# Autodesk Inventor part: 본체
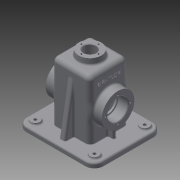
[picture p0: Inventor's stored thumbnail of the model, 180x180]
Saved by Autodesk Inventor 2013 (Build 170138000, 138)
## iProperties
Created: 2016-01
Part Number: 본체
Material: 일반
Document SubType Name: Modeling
Designer: Administrator
Density: 1 g/cm^3
Author: Administrator
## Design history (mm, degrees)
sketch "스케치1"
  geometry: L1 (-65, -57.5)-(65, -57.5); L2 (65, -57.5)-(65, 57.5); L3 (65, 57.5)-(-65, 57.5); L4 (-65, 57.5)-(-65, -57.5); 3 further points
  constraints: 8 end point, 2 midpoint, 2 parallel, 1 horizontal, 1 horizontal alignment, 1 perpendicular, 1 vertical alignment
  dimensions: "d0" = 130 distance of L2.end L3.end; "d2" = 115 distance of L1.end L2.end
extrude "돌출1" new body sketch "스케치1" distance "d3" = 8; taper "d4" = 0 deg
fillet "모깎기1" dims "d5" = 15
sketch "스케치2"
  geometry: L1 (-65, -42.5)-(-65, 42.5) reference; L2 (50, -57.5)-(-50, -57.5) reference; L3 (65, 42.5)-(65, -42.5) reference; L4 (-50, 57.5)-(50, 57.5) reference; L5 (-65, -42.5)-(-65, 42.5) reference; L6 (50, -57.5)-(-50, -57.5) reference; L7 (65, 42.5)-(65, -42.5) reference; L8 (-50, 57.5)-(50, 57.5) reference; L9 (-60, -42.5)-(-60, 42.5); L10 (-50, 52.5)-(50, 52.5); L11 (60, 42.5)-(60, -42.5); L12 (50, -52.5)-(-50, -52.5); A1 r 15 centre (-50, 42.5) between (-50, 57.5) and (-65, 42.5) reference; A2 r 15 centre (-50, -42.5) between (-65, -42.5) and (-50, -57.5) reference; A3 r 15 centre (50, -42.5) between (50, -57.5) and (65, -42.5) reference; A4 r 15 centre (50, 42.5) between (65, 42.5) and (50, 57.5) reference; A5 r 15 centre (-50, 42.5) between (-50, 57.5) and (-65, 42.5) reference; A6 r 15 centre (-50, -42.5) between (-65, -42.5) and (-50, -57.5) reference; A7 r 15 centre (50, -42.5) between (50, -57.5) and (65, -42.5) reference; A8 r 15 centre (50, 42.5) between (65, 42.5) and (50, 57.5) reference; A9 r 10 centre (-50, -42.5) between (-60, -42.5) and (-50, -52.5); A10 r 10 centre (-50, 42.5) between (-50, 52.5) and (-60, 42.5); A11 r 10 centre (50, 42.5) between (60, 42.5) and (50, 52.5); A12 r 10 centre (50, -42.5) between (50, -52.5) and (60, -42.5); 1 further point
  constraints: 8 end point, 8 point on circle, 4 centre point, 7 other
  dimensions: "d6" = 5 distance between parallel lines of L2 L12
extrude "돌출2" join sketch "스케치2" distance "d7" = 2; taper "d8" = 0 deg
sketch "스케치3"
  geometry: A1 r 10 centre (-50, -42.5) between (-60, -42.5) and (-50, -52.5) reference; A2 r 10 centre (50, -42.5) between (50, -52.5) and (60, -42.5) reference; A3 r 10 centre (50, 42.5) between (60, 42.5) and (50, 52.5) reference; A4 r 10 centre (-50, 42.5) between (-50, 52.5) and (-60, 42.5) reference; 1 further point
hole "구멍1" sketch "스케치3" at (50, -42.5), (-50, -42.5), (-50, 42.5), (50, 42.5) diameter "d9" = 5; stored, may be unused: countersink angle "d13" = 90 deg, drill point angle "d15" = 0 deg; dims "d10" = 6, "d11" = 4, "d12" = 2, "d14" = 13
sketch "스케치4"
  geometry: C1 r 2.5 at (50, 42.5) reference; C2 r 2.5 at (-50, -42.5) reference; C3 r 2.5 at (50, -42.5) reference; C4 r 2.5 at (-50, 42.5) reference; C5 r 7.5 at (-50, 42.5); C6 r 7.5 at (50, 42.5); C7 r 7.5 at (50, -42.5); C8 r 7.5 at (-50, -42.5); A1 r 15 centre (50, 42.5) between (65, 42.5) and (50, 57.5) reference; A2 r 15 centre (-50, 42.5) between (-50, 57.5) and (-65, 42.5) reference; A3 r 15 centre (-50, -42.5) between (-65, -42.5) and (-50, -57.5) reference; A4 r 15 centre (50, -42.5) between (50, -57.5) and (65, -42.5) reference; 1 further point
  constraints: 4 centre point, 4 coincident
  dimensions: "d16" = 15 diameter of C5; "d17" = 15 diameter of C6; "d18" = 15 diameter of C7; "d19" = 15 diameter of C8
extrude "돌출3" join sketch "스케치4" distance "d20" = 3; taper "d21" = 0 deg
fillet "모깎기2" dims "d22" = 3
fillet "모깎기3" dims "d23" = 3
sketch "스케치5"
  geometry: L1 (-32.5, 32.5)-(32.5, 32.5); L2 (32.5, 32.5)-(32.5, -32.5); L3 (32.5, -32.5)-(-32.5, -32.5); L4 (-32.5, -32.5)-(-32.5, 32.5); 3 further points
  constraints: 8 end point, 2 midpoint, 2 parallel, 1 horizontal, 1 horizontal alignment, 1 perpendicular, 1 vertical alignment
  dimensions: "d24" = 65 distance of L1.start L1.end; "d26" = 65 distance of L3.end L1.start
extrude "돌출4" join sketch "스케치5" distance "d27" = 100; taper "d28" = 0 deg
sketch "스케치6"
  geometry: L1 (27.5, -27.5)-(-27.5, -27.5); L2 (-27.5, -27.5)-(-27.5, 27.5); L3 (-27.5, 27.5)-(27.5, 27.5); L4 (27.5, 27.5)-(27.5, -27.5); 3 further points
  constraints: 8 end point, 2 midpoint, 2 parallel, 1 horizontal, 1 horizontal alignment, 1 perpendicular, 1 vertical alignment
  dimensions: "d31" = 55 distance of L1.start L1.end; "d33" = 55 distance of L3.end L1.start
extrude "돌출5" cut sketch "스케치6" distance "d34" = 105; taper "d35" = 0 deg
sketch "스케치7"
  geometry: C1 r 20 at (0, 0); 1 further point
  constraints: 1 centre point, 1 coincident
  dimensions: "d36" = 40 diameter of C1
extrude "돌출6" join sketch "스케치7" distance "d37" = 10; taper "d38" = 0 deg
feature "면 기울기1" dims angle "d39" = 5 deg
fillet "모깎기6" dims "d40" = 3
sketch "스케치8"
  geometry: C1 r 19.125 at (0, 0) reference; C2 r 10.5 at (0, 0)
  constraints: 1 centre point, 1 coincident
  dimensions: "d41" = 21 diameter of C2
extrude "돌출7" cut sketch "스케치8" distance "d42" = 15; taper "d43" = 0 deg
chamfer "모따기1" distance "d44" = 1; stored, may be unused: second distance "d45" = 2, angle "d46" = 45 deg
sketch "스케치9" dims "d47" = 29
  geometry: L1 (0, 0)-(0, 14.5); C1 r 11.5 at (0, 0) reference; 1 further point
  constraints: 2 coincident, 2 end point, 1 vertical, 1 vertical alignment, 2 other
hole "구멍2" sketch "스케치9" at (0, 14.5) diameter "d48" = 2.459; stored, may be unused: countersink angle "d52" = 90 deg, drill point angle "d54" = 118 deg; dims "d49" = 7, "d50" = 4, "d51" = 2, "d53" = 9
sketch "스케치10"
  geometry: L1 (10, -28)-(8, -28) reference; L2 (8, -28)-(8, -33) reference; L3 (8, -33)-(3, -33) reference; L4 (0, -30)-(0, -8) reference; L5 (0, 57)-(0, 79) reference; L6 (3, 82)-(8, 82) reference; L7 (8, 82)-(8, 77) reference; L8 (8, 77)-(10, 77) reference; L9 (10, 77)-(10, -28) reference; L10 (10, -28)-(8, -28) reference; L11 (8, -28)-(8, -33) reference; L12 (8, -33)-(3, -33) reference; L13 (0, -30)-(0, -8) reference; L14 (0, 57)-(0, 79) reference; L15 (3, 82)-(8, 82) reference; L16 (8, 82)-(8, 77) reference; L17 (8, 77)-(10, 77) reference; L18 (10, 77)-(10, -28) reference; L19 (0, -8)-(-100, -8) reference; L20 (-100, 57)-(0, 57) reference; L21 (0, -8)-(0, 57) reference; L22 (0, -8)-(-100, -8) reference; L23 (-100, 57)-(0, 57) reference; L24 (0, -8)-(0, 57) reference; L25 (-100, -8)-(-100, 57) reference; L26 (-100, -8)-(-100, 57) reference; C1 r 27.5 at (-45, 24.5); A1 r 3 centre (3, -30) between (0, -30) and (3, -33) reference; A2 r 3 centre (3, 79) between (3, 82) and (0, 79) reference; A3 r 3 centre (3, -30) between (0, -30) and (3, -33) reference; A4 r 3 centre (3, 79) between (3, 82) and (0, 79) reference; 2 further points
  constraints: 1 centre point, 1 horizontal alignment, 1 midpoint
  dimensions: "d58" = 55 diameter of C1; "d59" = 55 distance of point (10, 24.5) C1.centre
extrude "돌출8" join sketch "스케치10" distance "d60" = 15; taper "d61" = 0 deg
sketch "스케치11"
  geometry: C1 r 27.5 at (0, 0) reference; C2 r 17.5 at (0, 0); 1 further point
  constraints: 1 centre point, 1 coincident
  dimensions: "d62" = 35 diameter of C2
extrude "돌출9" cut sketch "스케치11" distance "d63" = 17; taper "d64" = 0 deg
sketch "스케치12" dims "d65" = 42
  geometry: L1 (0, 0)-(-21, 0); C1 r 27.5 at (0, 0) reference; 2 further points
  constraints: 2 coincident, 2 end point, 1 horizontal, 1 horizontal alignment, 2 other
hole "구멍3" sketch "스케치12" at (-21, 0) diameter "d66" = 3.242; stored, may be unused: countersink angle "d70" = 90 deg, drill point angle "d72" = 118 deg; dims "d67" = 8, "d68" = 4, "d69" = 2, "d71" = 10
sketch "스케치13"
  geometry: C1 r 17.5 at (0, 0) reference; C2 r 15 at (0, 0); 1 further point
  constraints: 1 centre point, 1 coincident
  dimensions: "d76" = 30 diameter of C2
extrude "돌출10" cut sketch "스케치13" distance "d77" = 3; taper "d78" = 0 deg
chamfer "모따기2" distance "d79" = 1; stored, may be unused: second distance "d80" = 2, angle "d81" = 45 deg
fillet "모깎기7" dims "d82" = 0.3
fillet "모깎기8" dims "d83" = 3
fillet "모깎기9" dims "d84" = 3
node "작업 평면1"
node "작업 평면2"
sketch "스케치15"
  geometry: L1 (100, 77)-(102, 77) reference; L2 (102, 77)-(102, 52) reference; L3 (102, 52)-(0, 52) reference; L4 (-3, 49)-(-3, 35) reference; L5 (-3, 35)-(-17, 35) reference; L6 (-17, 35)-(-18, 36) reference; L7 (-18, 36)-(-18, 37.77) reference; L8 (-18, 37.77)-(-9, 37.77) reference; L9 (-9, 37.77)-(-8.261, 39) reference; L10 (-8.261, 39)-(-9, 40.23) reference; L11 (-9, 40.23)-(-18, 40.23) reference; L12 (-18, 40.23)-(-18, 43.625) reference; L13 (-18, 43.625)-(-10.739, 44.26) reference; L14 (-8, 47.249)-(-8, 57) reference; L15 (-8, 57)-(92, 57) reference; L16 (92, 57)-(92, 79) reference; L17 (95, 82)-(100, 82) reference; L18 (100, 82)-(100, 77) reference; L19 (102, -28)-(100, -28) reference; L20 (100, -28)-(100, -33) reference; L21 (100, -33)-(95, -33) reference; L22 (92, -30)-(92, -8) reference; L23 (92, -8)-(-8, -8) reference; L24 (-8, -8)-(-8, 1.751) reference; L25 (-10.739, 4.74)-(-18, 5.375) reference; L26 (-18, 5.375)-(-18, 8.77) reference; L27 (-18, 8.77)-(-9, 8.77) reference; L28 (-9, 8.77)-(-8.261, 10) reference; L29 (-8.261, 10)-(-9, 11.229) reference; L30 (-9, 11.229)-(-18, 11.229) reference; L31 (-18, 11.229)-(-18, 13) reference; L32 (-18, 13)-(-17, 14) reference; L33 (-17, 14)-(-3, 14) reference; L34 (-3, 14)-(-3, 0) reference; L35 (0, -3)-(102, -3) reference; L36 (102, -3)-(102, -28) reference; L37 (92, -23)-(6.931, -8); L38 (92, 72)-(6.931, 57); L39 (6.931, -8)-(92, -8); L40 (92, -8)-(92, -23); L41 (6.931, 57)-(92, 57); L42 (92, 57)-(92, 72); A1 r 3 centre (0, 49) between (0, 52) and (-3, 49) reference; A2 r 3 centre (-11, 47.249) between (-10.739, 44.26) and (-8, 47.249) reference; A3 r 3 centre (95, 79) between (95, 82) and (92, 79) reference; A4 r 3 centre (95, -30) between (92, -30) and (95, -33) reference; A5 r 3 centre (-11, 1.751) between (-8, 1.751) and (-10.739, 4.74) reference; A6 r 3 centre (0, 0) between (-3, 0) and (0, -3) reference; 1 further point
  constraints: 12 end point, 4 point on line, 2 horizontal, 2 vertical
  dimensions: "d89" = 10 distance from line of L21 L37.start; "d90" = 100 deg angle of L22 L37; "d91" = 10 distance from line of L17 L38.start; "d92" = 100 deg angle of L16 L38
extrude "돌출12" join sketch "스케치15" stored distance "d93" = 10; taper "d94" = 0 deg
fillet "모깎기10" dims "d95" = 3
fillet "모깎기11" dims "d96" = 3
fillet "모깎기12" dims "d97" = 3
fillet "모깎기13" dims "d98" = 3
fillet "모깎기14" dims "d99" = 3
fillet "모깎기15" dims "d100" = 3
node "작업 평면3"
node "작업 평면4"
node "작업 평면5"
sketch "스케치17"
  geometry: L1 (12.74, 2.739)-(13.375, 10) reference; L2 (13.375, 10)-(16.77, 10) reference; L3 (16.77, 10)-(16.77, 1) reference; L4 (16.77, 1)-(18, 0.261) reference; L5 (18, 0.261)-(19.229, 1) reference; L6 (19.229, 1)-(19.229, 10) reference; L7 (19.229, 10)-(21, 10) reference; L8 (21, 10)-(22, 9) reference; L9 (22, 9)-(22, -5) reference; L10 (22, -5)-(8, -5) reference; L11 (5, -8)-(5, -40) reference; L12 (5, -40)-(2, -40) reference; L13 (2, -40)-(2, -37.8) reference; L14 (1.7, -37.5)-(-14, -37.5) reference; L15 (-14, -37.5)-(-15, -36.5) reference; L16 (-15, -36.5)-(-15, -35.621) reference; L17 (-15, -35.621)-(-5, -35.621) reference; L18 (-5, -35.621)-(-4.026, -34) reference; L19 (-4.026, -34)-(-5, -32.379) reference; L20 (-5, -32.379)-(-15, -32.379) reference; L21 (-15, -32.379)-(-15, -27.5) reference; L22 (-15, -27.5)-(0, -27.5) reference; L23 (0, -27.5)-(0, 0) reference; L24 (0, 0)-(9.751, 0) reference; L25 (55.249, 0)-(65, 0) reference; L26 (65, 0)-(65, -27.5) reference; L27 (65, -27.5)-(80, -27.5) reference; L28 (80, -27.5)-(80, -32.379) reference; L29 (80, -32.379)-(70, -32.379) reference; L30 (70, -32.379)-(69.026, -34) reference; L31 (69.026, -34)-(70, -35.621) reference; L32 (70, -35.621)-(80, -35.621) reference; L33 (80, -35.621)-(80, -36.5) reference; L34 (80, -36.5)-(79, -37.5) reference; L35 (79, -37.5)-(63.3, -37.5) reference; L36 (63, -37.8)-(63, -40) reference; L37 (63, -40)-(60, -40) reference; L38 (60, -40)-(60, -8) reference; L39 (57, -5)-(43, -5) reference; L40 (43, -5)-(43, 9) reference; L41 (43, 9)-(44, 10) reference; L42 (44, 10)-(45.77, 10) reference; L43 (45.77, 10)-(45.77, 1) reference; L44 (45.77, 1)-(47, 0.261) reference; L45 (47, 0.261)-(48.229, 1) reference; L46 (48.229, 1)-(48.229, 10) reference; L47 (48.229, 10)-(51.625, 10) reference; L48 (51.625, 10)-(52.26, 2.739) reference; L49 (92.5, -108)-(92.5, -110) reference; L50 (92.5, -110)-(60, -110) reference; L51 (60, -110)-(60, -70) reference; L52 (60, -70)-(63, -70) reference; L53 (63, -70)-(63, -72.2) reference; L54 (63.3, -72.5)-(79, -72.5) reference; L55 (79, -72.5)-(80, -73.5) reference; L56 (80, -73.5)-(80, -74.379) reference; L57 (80, -74.379)-(70, -74.379) reference; L58 (70, -74.379)-(69.026, -76) reference; L59 (69.026, -76)-(70, -77.621) reference; L60 (70, -77.621)-(80, -77.621) reference; L61 (80, -77.621)-(80, -82.5) reference; L62 (80, -82.5)-(65, -82.5) reference; L63 (65, -82.5)-(65, -100) reference; L64 (65, -100)-(94.5, -100) reference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; A1 r 3 centre (9.751, 3) between (9.751, 0) and (12.74, 2.739) reference; A2 r 3 centre (8, -8) between (8, -5) and (5, -8) reference; A3 r 0.3 centre (1.7, -37.8) between (2, -37.8) and (1.7, -37.5) reference; A4 r 3 centre (55.249, 3) between (52.26, 2.739) and (55.249, 0) reference; A5 r 0.3 centre (63.3, -37.8) between (63.3, -37.5) and (63, -37.8) reference; A6 r 3 centre (57, -8) between (60, -8) and (57, -5) reference; A7 r 0.3 centre (63.3, -72.2) between (63, -72.2) and (63.3, -72.5) reference; A8 r 3 centre (94.5, -103) between (97.5, -103) and (94.5, -100) reference; A9 r 3 centre (-29.5, -103) between (-29.5, -100) and (-32.5, -103) reference; A10 r 0.3 centre (1.7, -72.2) between (1.7, -72.5) and (2, -72.2) reference; 1 further point
  constraints: 14 end point, 4 horizontal, 3 point on line, 3 vertical
  dimensions: "d112" = 15 distance between parallel lines of L51 L86; "d113" = 20 distance between parallel lines of L89 L87; "d114" = 15 distance between parallel lines of L83 L90; "d115" = 20 distance between parallel lines of L85 L91
extrude "돌출14" join sketch "스케치17" stored distance "d116" = 6; taper "d117" = 0 deg
fillet "모깎기21" dims "d118" = 3
fillet "모깎기22" dims "d119" = 3
fillet "모깎기23" dims "d120" = 3
fillet "모깎기24" dims "d121" = 3
fillet "모깎기25" dims "d122" = 8
fillet "모깎기26" dims "d123" = 8
fillet "모깎기27" dims "d124" = 1
sketch "스케치18"
  geometry: L1 (-65, 19.125)-(-65, -19.125) reference; 3 further points
  constraints: 1 horizontal alignment, 1 midpoint, 1 other
  dimensions: "d125" = 27 distance from line of point (-38, 0) L1
feature "엠보싱1" sketch "스케치18" dims "d126" = 0.5, "d127" = 0
node "솔리드1"
pattern_circular "원형 패턴1" dims angle "d56" = 360 deg
pattern_circular "원형 패턴2" dims angle "d74" = 360 deg
mirror "대칭1"
node "투영된 루프1"
node "절단 모서리 투영1"
node "절단 모서리 투영2"
node "절단 모서리 투영4"
node "절단 모서리 투영6"
other parameters: "d106" = 32.5
